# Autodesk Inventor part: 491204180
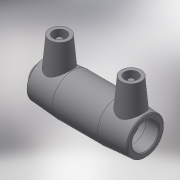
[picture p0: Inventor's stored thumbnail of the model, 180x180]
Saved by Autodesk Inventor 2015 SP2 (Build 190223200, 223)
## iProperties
Created: 2017-06
Part Number: 491204180
Material: Generic
Description: PLASSON END CAP 180
Document SubType Name: Modeling
Designer: KIM
Mass: 38.9236 g
Surface Area: 152.394 cm^2
Volume: 38.9236 cm^3
Density: 1 g/cm^3
Appearance: Default
Author: KIM
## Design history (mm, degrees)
derived "491204.ipt"
feature "Solid1::491204.ipt"
tag "TaggingFeature1"
body "Solid1"
other parameters: "d0" = 212, "d2" = 218, "d3" = 105, "d4" = 70.75, "d5" = 196.2, "d6" = 171, "d8" = 168 deg, "d10" = 42, "d11" = 14, "d13" = 226.4, "d14" = 17.6296, "d15" = 105, "d16" = 105, "d17" = 171, "d19" = 3.52592, "d20" = 168 deg, "d22" = 204.92, "d23" = 218, "d24" = 198.7724, "d25" = 135 deg, "d26" = 101.88, "d27" = 135 deg, "d29" = 116, "d30" = 15, "d31" = 90.56, "d34" = 5 deg, "d35" = 15, "d39" = 5 deg, "d41" = 4, "d42" = 14, "d43" = 0, "d45" = 4, "d46" = 14, "d47" = 0, "d48" = 283, "d49" = 1, "d51" = 144, "d52" = 5.094, "d53" = 198, "d54" = 5.094, "d56" = 18, "d57" = 5.4, "d60" = 42.45, "d61" = 3.6, "d63" = 283, "d64" = 1, "d66" = 144, "d67" = 36, "d68" = 198, "d69" = 5.66, "d70" = 0, "d71" = 5.094, "d72" = 3, "d73" = 0, "d74" = 30.45, "d75" = 10.15, "d76" = 3, "d77" = 0, "L_" = 283, "L_1" = 105, "D_" = 218, "A_" = 116, "d_2" = 12, "L_0" = 212, "d55" = 18
